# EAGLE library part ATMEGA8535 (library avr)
MICROCONTROLLER 8 Kbytes FLASH 512 bytes SRAM 512 bytes EEPROM USART 8-channel 10 bit ADC
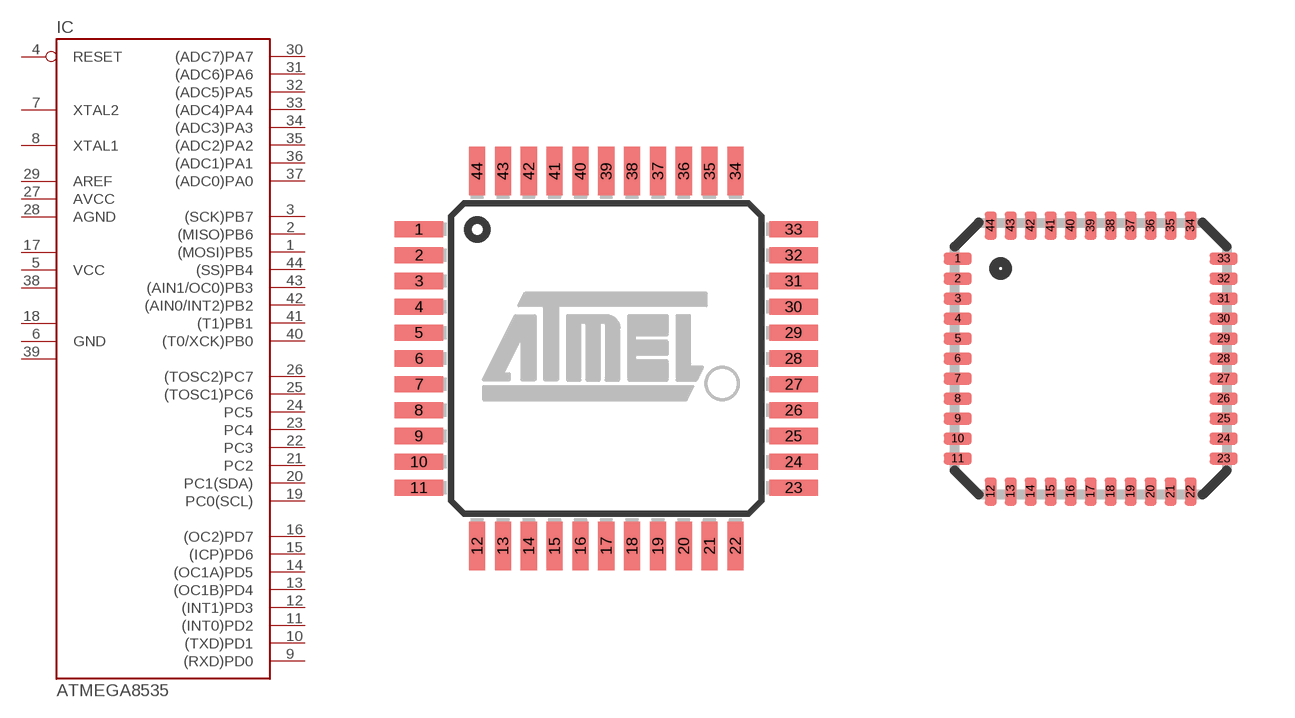
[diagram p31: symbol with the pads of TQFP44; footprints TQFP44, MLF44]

Designator prefix IC

## ATMEGA8535-16A, ATMEGA8535L-8A  [TQFP44]
1  (MOSI)PB5
2  (MISO)PB6
3  (SCK)PB7
4  RESET  in
5  VCC  pwr
6  GND  pwr
7  XTAL2
8  XTAL1
9  (RXD)PD0
10  (TXD)PD1
11  (INT0)PD2
12  (INT1)PD3
13  (OC1B)PD4
14  (OC1A)PD5
15  (ICP)PD6
16  (OC2)PD7
17  VCC1  pwr
18  GND1  pwr
19  PC0(SCL)
20  PC1(SDA)
21  PC2
22  PC3
23  PC4
24  PC5
25  (TOSC1)PC6
26  (TOSC2)PC7
27  AVCC  pwr
28  AGND  pwr
29  AREF  pwr
30  (ADC7)PA7
31  (ADC6)PA6
32  (ADC5)PA5
33  (ADC4)PA4
34  (ADC3)PA3
35  (ADC2)PA2
36  (ADC1)PA1
37  (ADC0)PA0
38  VCC2  pwr
39  GND2  pwr
40  (T0/XCK)PB0
41  (T1)PB1
42  (AIN0/INT2)PB2
43  (AIN1/OC0)PB3
44  (SS)PB4

## ATMEGA8535-16M, ATMEGA8535L-8M  [MLF44]
Pads as for TQFP44

## ATMEGA8535-16J, ATMEGA8535L-8J  [PLCC44]
1  GND  pwr
2  (T0/XCK)PB0
3  (T1)PB1
4  (AIN0/INT2)PB2
5  (AIN1/OC0)PB3
6  (SS)PB4
7  (MOSI)PB5
8  (MISO)PB6
9  (SCK)PB7
10  RESET  in
11  VCC  pwr
12  GND1  pwr
13  XTAL2
14  XTAL1
15  (RXD)PD0
16  (TXD)PD1
17  (INT0)PD2
18  (INT1)PD3
19  (OC1B)PD4
20  (OC1A)PD5
21  (ICP)PD6
22  (OC2)PD7
23  VCC1  pwr
24  GND2  pwr
25  PC0(SCL)
26  PC1(SDA)
27  PC2
28  PC3
29  PC4
30  PC5
31  (TOSC1)PC6
32  (TOSC2)PC7
33  AVCC  pwr
34  AGND  pwr
35  AREF  pwr
36  (ADC7)PA7
37  (ADC6)PA6
38  (ADC5)PA5
39  (ADC4)PA4
40  (ADC3)PA3
41  (ADC2)PA2
42  (ADC1)PA1
43  (ADC0)PA0
44  VCC2  pwr

## ATMEGA8535-16J-SMD, ATMEGA8535L-8J-SMD  [PLCC-SM44]
Pads as for PLCC44

## ATMEGA8535-16J-SO, ATMEGA8535L-8J-SO  [S44]
Pads as for PLCC44

## Footprint TQFP44 (pad centres in mm)
Thin Plasic Quad Flat Package
smd 1.5 x 0.5: 1 -5.8,4; 2 -5.8,3.2; 3 -5.8,2.4; 4 -5.8,1.6; 5 -5.8,0.8; 6 -5.8,0; 7 -5.8,-0.8; 8 -5.8,-1.6; 9 -5.8,-2.4; 10 -5.8,-3.2; 11 -5.8,-4; 23 5.8,-4; 24 5.8,-3.2; 25 5.8,-2.4; 26 5.8,-1.6; 27 5.8,-0.8; 28 5.8,0; 29 5.8,0.8; 30 5.8,1.6; 31 5.8,2.4; 32 5.8,3.2; 33 5.8,4
smd 0.5 x 1.5: 12 -4,-5.8; 13 -3.2,-5.8; 14 -2.4,-5.8; 15 -1.6,-5.8; 16 -0.8,-5.8; 17 0,-5.8; 18 0.8,-5.8; 19 1.6,-5.8; 20 2.4,-5.8; 21 3.2,-5.8; 22 4,-5.8; 34 4,5.8; 35 3.2,5.8; 36 2.4,5.8; 37 1.6,5.8; 38 0.8,5.8; 39 0,5.8; 40 -0.8,5.8; 41 -1.6,5.8; 42 -2.4,5.8; 43 -3.2,5.8; 44 -4,5.8

## Footprint MLF44 (pad centres in mm)
44M1 Micro Lead Frame package (MLF)
smd 0.7 x 0.3: 1 -3.325,2.5; 2 -3.325,2; 3 -3.325,1.5; 4 -3.325,1; 5 -3.325,0.5; 6 -3.325,0; 7 -3.325,-0.5; 8 -3.325,-1; 9 -3.325,-1.5; 10 -3.325,-2; 11 -3.325,-2.5; 23 3.325,-2.5; 24 3.325,-2; 25 3.325,-1.5; 26 3.325,-1; 27 3.325,-0.5; 28 3.325,0; 29 3.325,0.5; 30 3.325,1; 31 3.325,1.5; 32 3.325,2; 33 3.325,2.5
smd 0.3 x 0.7: 12 -2.5,-3.325; 13 -2,-3.325; 14 -1.5,-3.325; 15 -1,-3.325; 16 -0.5,-3.325; 17 0,-3.325; 18 0.5,-3.325; 19 1,-3.325; 20 1.5,-3.325; 21 2,-3.325; 22 2.5,-3.325; 34 2.5,3.325; 35 2,3.325; 36 1.5,3.325; 37 1,3.325; 38 0.5,3.325; 39 0,3.325; 40 -0.5,3.325; 41 -1,3.325; 42 -1.5,3.325; 43 -2,3.325; 44 -2.5,3.325

## Footprint PLCC44 (pad centres in mm)
Plastic J-Leaded Chip Carrier
smd 1.8 x 0.76: 1 -7.86,0; 2 -7.86,-1.27; 3 -7.86,-2.54; 4 -7.86,-3.81; 5 -7.86,-5.08; 6 -7.86,-6.35; 18 7.86,-6.35; 19 7.86,-5.08; 20 7.86,-3.81; 21 7.86,-2.54; 22 7.86,-1.27; 23 7.86,0; 24 7.86,1.27; 25 7.86,2.54; 26 7.86,3.81; 27 7.86,5.08; 28 7.86,6.35; 40 -7.86,6.35; 41 -7.86,5.08; 42 -7.86,3.81; 43 -7.86,2.54; 44 -7.86,1.27
smd 0.76 x 1.8: 7 -6.35,-7.86; 8 -5.08,-7.86; 9 -3.81,-7.86; 10 -2.54,-7.86; 11 -1.27,-7.86; 12 0,-7.86; 13 1.27,-7.86; 14 2.54,-7.86; 15 3.81,-7.86; 16 5.08,-7.86; 17 6.35,-7.86; 29 6.35,7.86; 30 5.08,7.86; 31 3.81,7.86; 32 2.54,7.86; 33 1.27,7.86; 34 0,7.86; 35 -1.27,7.86; 36 -2.54,7.86; 37 -3.81,7.86; 38 -5.08,7.86; 39 -6.35,7.86

## Footprint PLCC-SM44 (pad centres in mm)
SMD Plastic J-Leaded Chip Carrier Socket
smd 2.591 x 0.66: 1 -8.89,0; 2 -8.89,-1.27; 3 -8.89,-2.54; 4 -8.89,-3.81; 5 -8.89,-5.08; 6 -8.89,-6.35; 18 8.89,-6.35; 19 8.89,-5.08; 20 8.89,-3.81; 21 8.89,-2.54; 22 8.89,-1.27; 23 8.89,0; 24 8.89,1.27; 25 8.89,2.54; 26 8.89,3.81; 27 8.89,5.08; 28 8.89,6.35; 40 -8.89,6.35; 41 -8.89,5.08; 42 -8.89,3.81; 43 -8.89,2.54; 44 -8.89,1.27
smd 0.66 x 2.591: 7 -6.35,-8.89; 8 -5.08,-8.89; 9 -3.81,-8.89; 10 -2.54,-8.89; 11 -1.27,-8.89; 12 0,-8.89; 13 1.27,-8.89; 14 2.54,-8.89; 15 3.81,-8.89; 16 5.08,-8.89; 17 6.35,-8.89; 29 6.35,8.89; 30 5.08,8.89; 31 3.81,8.89; 32 2.54,8.89; 33 1.27,8.89; 34 0,9.017; 35 -1.27,8.89; 36 -2.54,8.89; 37 -3.81,8.89; 38 -5.08,8.89; 39 -6.35,8.89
